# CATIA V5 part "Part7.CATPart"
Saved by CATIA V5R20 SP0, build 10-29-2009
Part number: Part7
Bounding box of the stored display mesh (mm): x -86 to 75, y 0 to 27, z 0 to 21.997
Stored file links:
  E:\Ehsan\Catia\Tamrin\DMU\2\Part7.CATPart
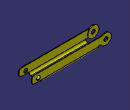
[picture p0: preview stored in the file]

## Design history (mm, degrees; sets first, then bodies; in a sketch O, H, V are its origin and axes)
Body1 (main body)
  Sketch1 on zx-plane, origin (0, 0, 0), H (-1, 0, 0), V (0, 0, 1)
    line L1 (-75, 0) -> (75, 0)
    length L1 = 150
    midpoint: L1 O
    horizontal: L1 H
  Pad1: profile Sketch1, direction (0, 1, 0), length 13.5, thin wall 20
  Fillet1: radius 5, on edge [start face of Pad1 | face of Pad1]
  Shell1: IntOffset 1, Face (face of Pad1; end face of Pad1; face of Pad1; face of Pad1), ExtOffset 0
  Sketch2 on zx-plane, origin (0, 0, 0), H (-1, 0, 0), V (0, 0, 1)
    point P1 (91.4177, 6)
    line L1 (91.4177, 6) -> (60, 6)
    line L2 (60, 6) -> (60, -4.0828)
    line L3 (60, -4.0828) -> (91.4177, -4.0828)
    line L4 (91.4177, -4.0828) -> (91.4177, 6)
    reference projected line E1 (75, 0) -> (75, 20) from edge [start face of Pad1 | face of Pad1]
    distance P1 H = 6
    distance L2 E1 = 15
    horizontal: L1 H, L3 H
    vertical: L2 V, L4 V
  Pocket1: profile Sketch2, direction (0, 1, 0), length 31
  Sketch3 on start face of Pad1, origin (0, 0, 0), H (1, 0, 0), V (0, 0, 1)
    circle A1 centre (-75, 11) radius 11
    point P1 (-75, 11)
    distance P1 H = 11
    distance P1 V = 75
    radius A1 = 11
  Pad2: profile Sketch3, direction (0, 1, 0), length 1.5
  Sketch4 on face of Pad2, origin (0, 0, 0), H (1, 0, 0), V (0, 0, 1)
    circle A1 centre (-75, 11) radius 4
    reference projected circle E1 centre (-75, 11) radius 11 from edge [face of Pad2 from Sketch3.A1 | face of Pad2]
    circle A2 centre (61.9, 11) radius 4
    point P2 (61.9, 11)
    reference projected line E2 (75, 20) -> (75, 0) from edge [face of Pad2 | face of Pad1]
    radius A1 = 4
    distance P2 H = 11
    radius A2 = 4
    distance A2 E2 = 9.1
    concentricity: A1 E1
  Pocket2: profile Sketch4, direction (0, 1, 0), length 1.5
  Sketch5 on face of Pad2, origin (0, 0, 0), H (1, 0, 0), V (0, 0, 1)
    line L1 (55, 5) -> (80.8396, 5)
    line L2 (80.8396, 5) -> (80.8396, -2.8568)
    line L3 (80.8396, -2.8568) -> (55, -2.8568)
    line L4 (55, -2.8568) -> (55, 5)
    reference projected line E1 (75, 20) -> (75, 0) from edge [face of Pad2 | face of Pad1]
    reference projected line E2 (75, 5) -> (-75, 5) from edge [face of Pad2 | face of Fillet1]
    distance L4 E1 = 20
    distance L1 E2 = 0
    horizontal: L1 H, L3 H
    vertical: L2 V, L4 V
  Pocket3: profile Sketch5, direction (0, 1, 0), length 31
  Fillet2: radius 5, on edge [face of Pad1 | face of Pad1]; edge [face of Pocket3 from Sketch5.L1 | face of Pad1]
  Mirror1: of the body so far, about end face of Pad1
